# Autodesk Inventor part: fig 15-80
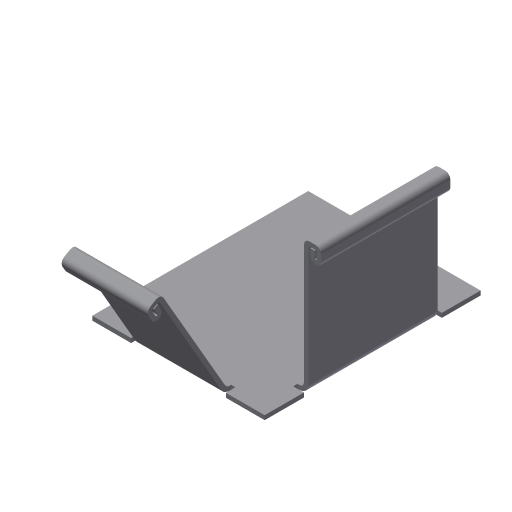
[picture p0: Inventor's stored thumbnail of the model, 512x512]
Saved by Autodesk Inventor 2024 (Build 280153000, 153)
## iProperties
Shininess: 77.0
Angle Display Precision: 2
Document Length Units: 11269
Document Angle Units: 11279
Document Time Units: 11290
Document Mass Units: 11283
Document Length Units Precision: 3
Document Angle Units Precision: 2
Compacted: True
Created: 2002-04
Part Number: fig 15-80
Document SubType Name: Sheet Metal
Density: 1 g/cm^3
Sheet Metal Rule: Default
Material: Generic
Appearance: Default
Density: 0.0
Volumn: 0.0
Area: 0.0
PropertySet Name: Model Information
Control State: 0
Master: False
Checked Out: False
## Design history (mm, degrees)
node "Face1"
  sketch "Sketch1"
    geometry: L1 (-17.882, 11.882)-(2.118, 11.882); L2 (2.118, 11.882)-(2.118, -13.176); L3 (2.118, -13.176)-(-17.882, -13.176); L4 (-17.882, -13.176)-(-17.882, 11.882)
    constraints: 8 end point, 2 parallel, 1 horizontal, 1 perpendicular
    dimensions: "d17" = 20 distance of L2.end L3.end
node "Flange2"
node "Flange3"
feature "Hem8" dims "d82" = 0.5 (= BendReliefWidth), "d83" = 0.25 (= BendReliefDepth), "d84" = 1 (= MinimumRemnant), "d85" = 0.5 (= BendRadius), "d108" = 2 (= 4 x Thickness), "d109" = 0.25 (= 0.5 x Thickness), "d110" = 0.125 (= 0.5 x d109), "d114" = 0.5 (= Thickness), "SeamGap" = 0.01
feature "Hem9" dims "d89" = 0.5 (= BendReliefWidth), "d90" = 0.25 (= BendReliefDepth), "d91" = 1 (= MinimumRemnant), "d92" = 0.5 (= BendRadius), "d111" = 2 (= 4 x Thickness), "d112" = 0.25 (= 0.5 x Thickness), "d113" = 0.125 (= 0.5 x d112), "d114" = 0.5 (= Thickness), "SeamGap" = 0.01
body "Solid1"
face "Plate1" dims "d114" = 0.5 (= Thickness)
sketch "Sketch3"
  geometry: L1 (5, 0)-(20, 0); L2 (20, 0)-(20, 15); L3 (20, 15)-(5, 15); L4 (5, 15)-(5, 0)
  constraints: 8 end point
face "Plate3" dims "d6" = 15, "d7" = 90 deg, "d8" = 0.5 (= BendRadius), "d18" = 5, "d19" = 15, "d114" = 0.5 (= Thickness), "MinimumRemnant" = 1 (= 2 x Thickness), "BendReliefWidth" = 0.5 (= Thickness)
bend "Bend2" dims "d6" = 15, "d7" = 90 deg, "d8" = 0.5 (= BendRadius), "d56" = 0.5 (= BendReliefWidth), "d57" = 0.25 (= BendReliefDepth), "d58" = 1 (= MinimumRemnant), "d114" = 0.5 (= Thickness), "SeamGap" = 0.01, "MinimumRemnant" = 1 (= 2 x Thickness), "BendReliefWidth" = 0.5 (= Thickness), "TransitionRadius" = 0.5 (= BendRadius)
sketch "Sketch6"
  geometry: L1 (15, 0)-(5, 0); L2 (5, 0)-(5, 15); L3 (5, 15)-(15, 15); L4 (15, 15)-(15, 0)
  constraints: 8 end point
face "Plate4" dims "d20" = 5, "d21" = 10, "d23" = 15, "d24" = 60 deg, "d25" = 0.5 (= BendRadius), "d114" = 0.5 (= Thickness), "MinimumRemnant" = 1 (= 2 x Thickness), "BendReliefWidth" = 0.5 (= Thickness)
bend "Bend3" dims "d22" = 0.5 (= BendRadius), "d23" = 15, "d24" = 60 deg, "d25" = 0.5 (= BendRadius), "d59" = 0.5 (= BendReliefWidth), "d60" = 0.25 (= BendReliefDepth), "d61" = 1 (= MinimumRemnant), "d114" = 0.5 (= Thickness), "SeamGap" = 0.01, "MinimumRemnant" = 1 (= 2 x Thickness), "BendReliefWidth" = 0.5 (= Thickness)
sketch "Sketch12"
  geometry: L1 (0.433, 0.25)-(0, 0); L2 (-0.171, 0.046)-(-0.82, -0.329); L3 (-0.866, -0.5)-(-0.491, -1.15); L4 (-0.275, -1.025)-(-0.65, -0.375); L5 (-0.65, -0.375)-(-0.217, -0.125); L6 (-0.217, -0.125)-(0.158, -0.775); L7 (-0.924, -1.4)-(-1.299, -0.75); L8 (-1.07, 0.104)-(-0.421, 0.479); A1 r 0.125 centre (-0.108, -0.063) between (0, 0) and (-0.171, 0.046); A2 r 0.125 centre (-0.758, -0.438) between (-0.82, -0.329) and (-0.866, -0.5); A3 r 0.125 centre (-0.383, -1.087) between (-0.491, -1.15) and (-0.275, -1.025); A4 r 0.625 centre (-0.383, -1.087) between (-0.924, -1.4) and (0.158, -0.775); A5 r 0.625 centre (-0.758, -0.438) between (-1.07, 0.104) and (-1.299, -0.75); A6 r 0.625 centre (-0.108, -0.063) between (0.433, 0.25) and (-0.421, 0.479); 2 further points
  constraints: 16 end point, 12 point on circle
sketch "Sketch13"
  geometry: L1 (0.5, 0)-(0, 0); L2 (-0.125, 0.125)-(-0.875, 0.125); L3 (-1, 0)-(-1, -0.75); L4 (-0.75, -0.75)-(-0.75, 0); L5 (-0.75, 0)-(-0.25, 0); L6 (-0.25, 0)-(-0.25, -0.75); L7 (-1.5, -0.75)-(-1.5, 0); L8 (-0.875, 0.625)-(-0.125, 0.625); A1 r 0.125 centre (-0.125, 0) between (0, 0) and (-0.125, 0.125); A2 r 0.125 centre (-0.875, 0) between (-0.875, 0.125) and (-1, 0); A3 r 0.125 centre (-0.875, -0.75) between (-1, -0.75) and (-0.75, -0.75); A4 r 0.625 centre (-0.875, -0.75) between (-1.5, -0.75) and (-0.25, -0.75); A5 r 0.625 centre (-0.875, 0) between (-0.875, 0.625) and (-1.5, 0); A6 r 0.625 centre (-0.125, 0) between (0.5, 0) and (-0.125, 0.625); 2 further points
  constraints: 16 end point, 12 point on circle
other parameters: "Thickness" = 0.5, "BendRadius" = 0.5 (= Thickness), "BendReliefDepth" = 0.25 (= 0.5 x Thickness), "CornerReliefSize" = 2 (= 4 x Thickness), "d0" = 0.5 (= BendRadius), "d5" = 0.5 (= BendRadius), "d26" = 0.5 (= BendRadius), "d30" = 0.5 (= BendRadius), "JacobiRadiusSize" = 0.5 (= Thickness), "GapSize" = 0.5 (= Thickness)
